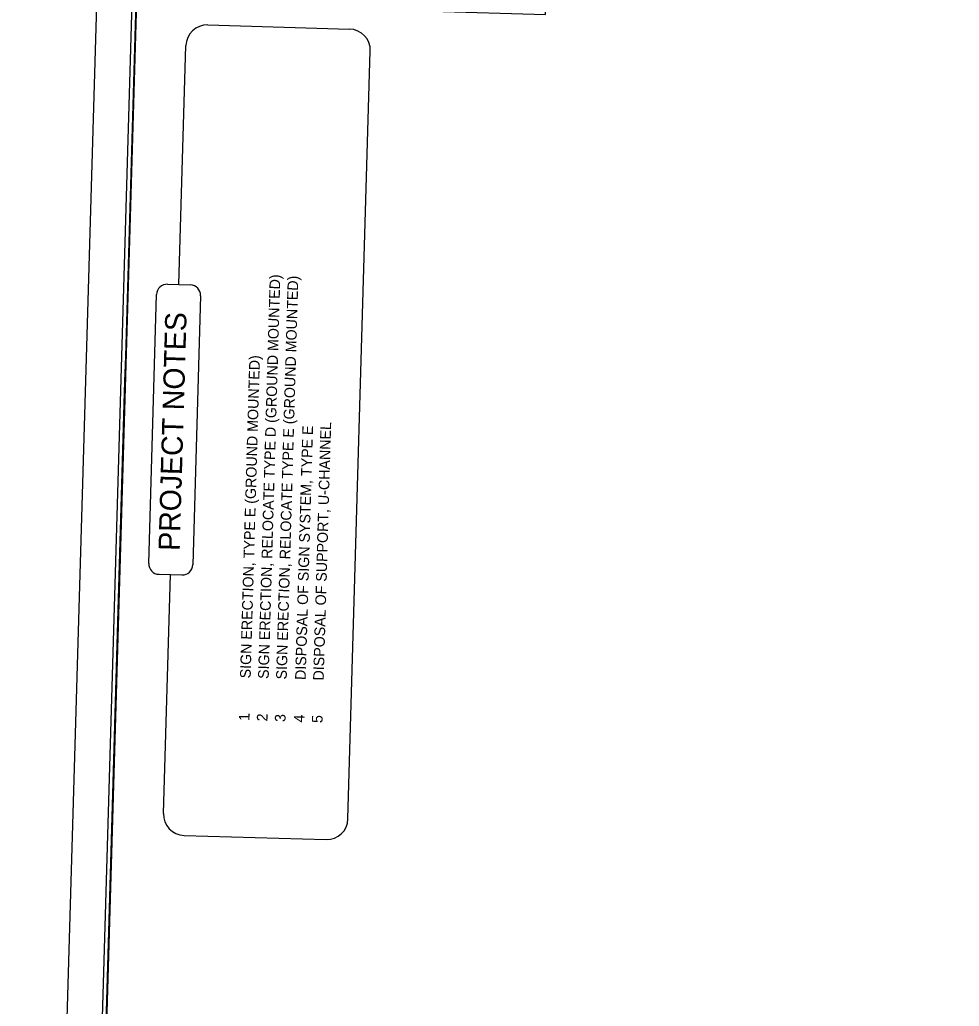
# Model space of a CAD drawing. Extents: x 2096999 to 2102576, y 682920 to 687015.
# Drawn here: x 2096999 to 2097529, y 686071 to 686627 of the extents above; entities that cross this region are included whole.
import ezdxf

# ---------------------------------------------------------------- set-up
doc = ezdxf.new("R2010")
doc.units = 0
for name, color, linetype in [('Default', 7, 'Continuous'), ('Scratch_Level_2', 7, 'Continuous'), ('Sheet Plan CELL', 7, 'Continuous'), ('Sheet Plot Border Inside CELL', 7, 'Continuous'), ('Sheet Plot Border Outside CELL', 7, 'Continuous'), ('Sheet Title CELL', 7, 'Continuous')]:
    doc.layers.add(name, color=color, linetype=linetype)

msp = doc.modelspace()

# ---------------------------------------------------------------- linework, layer by layer
at = {"layer": 'Scratch_Level_2'}
msp.add_lwpolyline([(2097234.32, 685317.78), (2097026.76, 685323.81), (2097058.72, 686423.24), (2097059.31, 686437.01), (2097065.14, 686636.69), (2097214.22, 686632.33), (2097231.8, 686631.82), (2097295.87, 686629.95), (2097298.79, 686729.78), (2098044.58, 686708.09), (2098037.23, 686456.47), (2098110.07, 686454.34), (2098090.85, 685704.42)], close=True, dxfattribs=at)
at = {"layer": 'Sheet Plan CELL'}
msp.add_lwpolyline([(2097070.6, 686823.38), (2097026.77, 685323.98), (2098076.32, 685293.3), (2098120.15, 686792.67)], close=True, dxfattribs=at)
msp.add_lwpolyline([(2097070.6, 686823.38), (2097026.77, 685323.98), (2098076.32, 685293.3), (2098120.15, 686792.67)], close=True, dxfattribs=at)
at = {"layer": 'Sheet Plot Border Inside CELL'}
msp.add_lwpolyline([(2098074.34, 685139.8), (2098123.02, 686805.08), (2097068.48, 686835.92), (2097019.79, 685170.63)], close=True, dxfattribs=at)
msp.add_lwpolyline([(2098074.34, 685139.8), (2098123.02, 686805.08), (2097068.48, 686835.92), (2097019.79, 685170.63)], close=True, dxfattribs=at)
at = {"layer": 'Sheet Plot Border Outside CELL'}
msp.add_lwpolyline([(2098093.96, 685126.22), (2098143.15, 686809.01), (2097048.62, 686841), (2096999.42, 685158.22)], close=True, dxfattribs=at)
msp.add_lwpolyline([(2098093.96, 685126.22), (2098143.15, 686809.01), (2097048.62, 686841), (2096999.42, 685158.22)], close=True, dxfattribs=at)
at = {"layer": 'Sheet Title CELL'}
for p, q in [((2097105.41, 686624.05), (2097185.39, 686621.73)), ((2097089.15, 686477.68), (2097093.07, 686612.41)), ((2097184.45, 686176.28), (2097197.04, 686609.39)), ((2097082.72, 686477.86), (2097095.57, 686477.49)), ((2097072.14, 686320.4), (2097076.55, 686472.04)), ((2097101.4, 686471.32), (2097096.99, 686319.67)), ((2097077.97, 686314.22), (2097090.82, 686313.85)), ((2097080.48, 686179.3), (2097084.39, 686314.04)), ((2097092.12, 686166.96), (2097172.11, 686164.64))]:
    msp.add_line(p, q, dxfattribs=at)
for centre, radius, start, end in [((2097105.06, 686612.06), 12, 88.3348, 178.3348), ((2097185.05, 686609.73), 12, 358.3348, 88.3348), ((2097082.55, 686471.86), 6, 88.3348, 178.3348), ((2097095.4, 686471.49), 6, 358.3348, 88.3348), ((2097078.14, 686320.22), 6, 178.3348, 268.3348), ((2097090.99, 686319.85), 6, 268.3348, 358.3348), ((2097092.47, 686178.96), 12, 178.3348, 268.3348), ((2097172.46, 686176.63), 12, 268.3348, 358.3348)]:
    msp.add_arc(centre, radius, start, end, dxfattribs=at)

# ---------------------------------------------------------------- texts
at = {"layer": 'Default'}
for s, height, p in [('SIGN ERECTION, RELOCATE TYPE D (GROUND MOUNTED)', 6, (2097139.74, 686255.17)), ('SIGN ERECTION, RELOCATE TYPE E (GROUND MOUNTED)', 6, (2097149.9, 686254.87)), ('PROJECT NOTES', 12, (2097089.6, 686327.33)), ('SIGN ERECTION, TYPE E (GROUND MOUNTED)', 6, (2097129.57, 686255.47)), ('DISPOSAL OF SIGN SYSTEM, TYPE E', 6, (2097160.61, 686254.56)), ('DISPOSAL OF SUPPORT, U-CHANNEL', 6, (2097170.77, 686254.27)), ('1', 6, (2097128.87, 686231.48)), ('2', 6, (2097139.04, 686231.18)), ('3', 6, (2097149.2, 686230.88)), ('4', 6, (2097159.91, 686230.57)), ('5', 6, (2097170.08, 686230.28))]:
    msp.add_text(s, height=height, rotation=88.3348, dxfattribs=at).set_placement(p)

doc.saveas('drawing.dxf')
